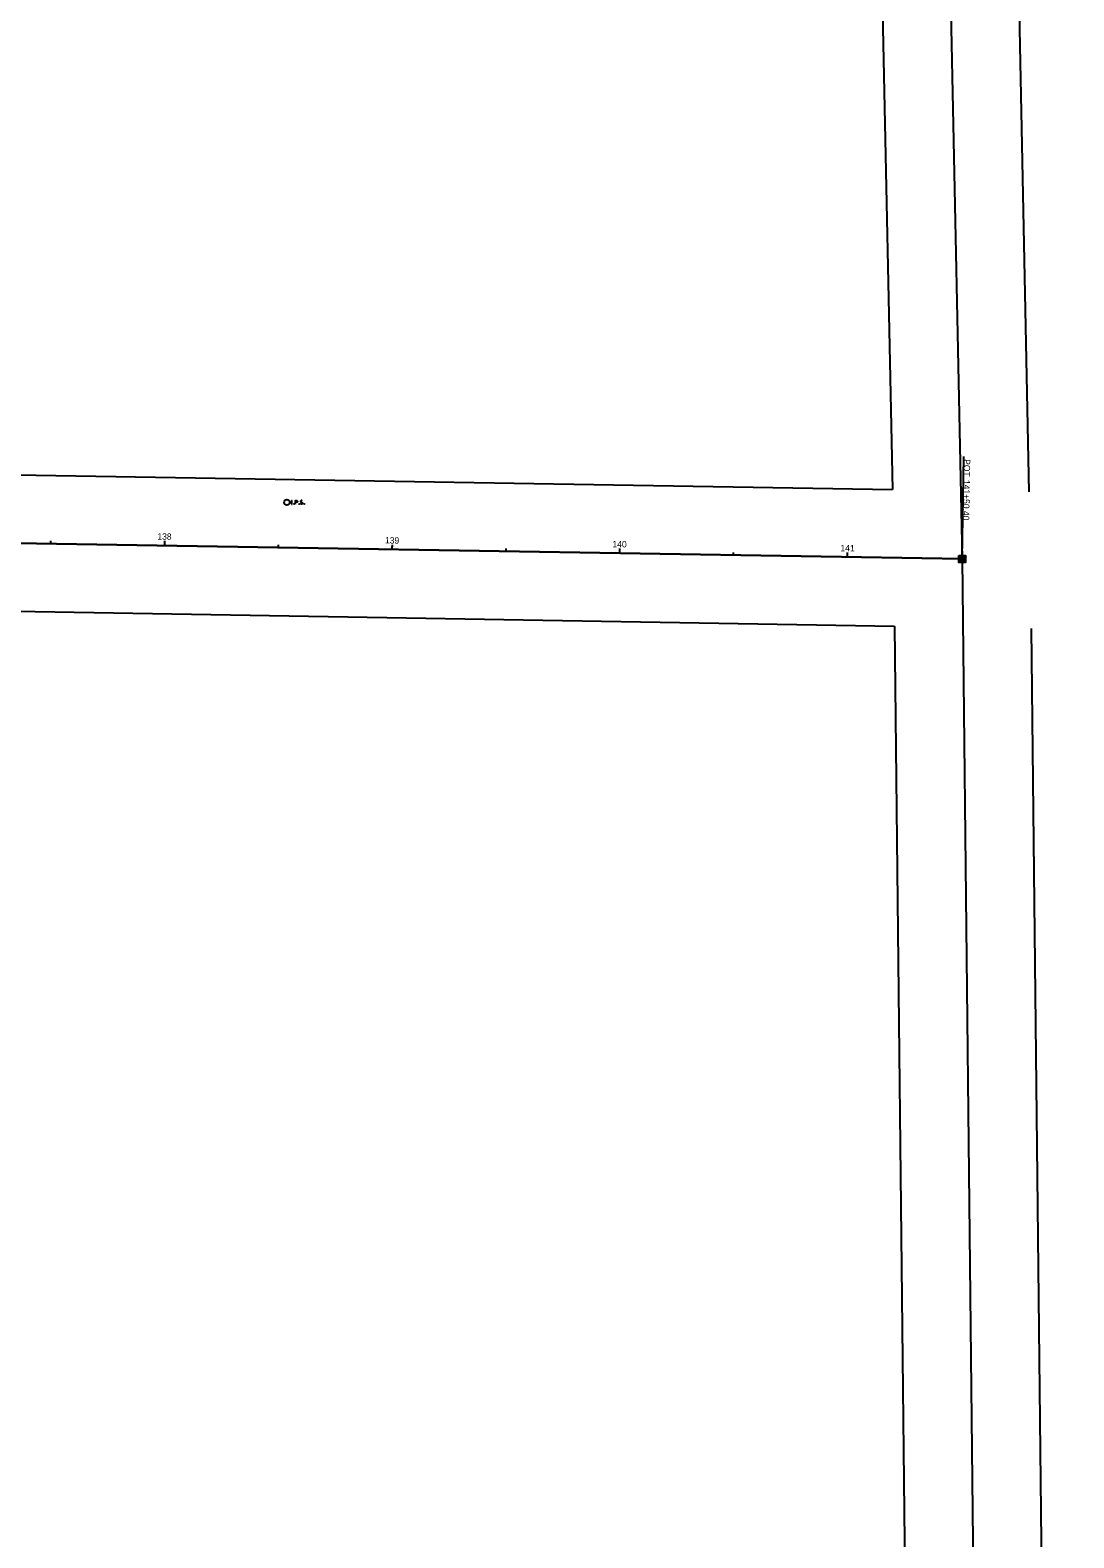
# Model space of a CAD drawing. Extents: x 2003596 to 2006933, y 570827 to 573780.
# Drawn here: x 2006475 to 2006933, y 572153 to 572815 of the extents above; entities that cross this region are included whole.
import ezdxf

# ---------------------------------------------------------------- set-up
doc = ezdxf.new("R2010")
doc.units = 0
for name, color, linetype in [('DT_X_Spot_Elev', 7, 'Continuous'), ('DV_X_Lot_Line', 7, 'Continuous'), ('GE_X_Alignment', 7, 'Continuous'), ('GE_X_Alignment_1000_Cardinal_Points', 7, 'Continuous'), ('GE_X_Alignment_1000_Stations', 7, 'Continuous'), ('GE_X_Alignment_100_Cardinal_Points', 7, 'Continuous'), ('GE_X_Alignment_100_Stations', 7, 'Continuous'), ('GE_X_Alignment_500_Cardinal_Points', 7, 'Continuous'), ('GE_X_Alignment_500_Stations', 7, 'Continuous'), ('RW_X_CL', 7, 'Continuous'), ('RW_X_Esmt_SH', 7, 'Continuous'), ('SC_Scratch9', 7, 'Continuous'), ('SV_P_Mon_Cells_Set', 7, 'Continuous'), ('SV_X_Control_Cells_Found', 7, 'Continuous')]:
    doc.layers.add(name, color=color, linetype=linetype)

msp = doc.modelspace()

# ---------------------------------------------------------------- linework, layer by layer
at = {"layer": 'DT_X_Spot_Elev'}
for p, q in [((2006865.66, 573476.51), (2006884.1, 572582.77)), ((2006884.1, 572582.77), (2006023.62, 572597.25))]:
    msp.add_line(p, q, dxfattribs=at)
at = {"layer": 'DV_X_Lot_Line'}
for p, q in [((2006865.66, 573476.51), (2006884.1, 572582.77)), ((2006884.1, 572582.77), (2006903.2, 570827.76))]:
    msp.add_line(p, q, dxfattribs=at)
at = {"layer": 'GE_X_Alignment'}
msp.add_line((2006023.62, 572597.25), (2006884.1, 572582.77), dxfattribs=at)
at = {"layer": 'GE_X_Alignment_1000_Cardinal_Points'}
msp.add_line((2006884.1, 572582.77), (2006884.86, 572627.76), dxfattribs=at)
msp.add_circle((2006884.1, 572582.77), 0.6, dxfattribs=at)
at = {"layer": 'GE_X_Alignment_1000_Stations'}
msp.add_line((2006733.72, 572585.3), (2006733.75, 572587.3), dxfattribs=at)
at = {"layer": 'GE_X_Alignment_100_Cardinal_Points'}
msp.add_line((2006884.1, 572582.77), (2006884.86, 572627.76), dxfattribs=at)
msp.add_circle((2006884.1, 572582.77), 0.6, dxfattribs=at)
at = {"layer": 'GE_X_Alignment_100_Stations'}
for p, q in [((2006483.76, 572589.51), (2006483.78, 572590.71)), ((2006533.75, 572588.67), (2006533.78, 572590.67)), ((2006583.74, 572587.82), (2006583.76, 572589.02)), ((2006633.73, 572586.98), (2006633.77, 572588.98)), ((2006683.73, 572586.14), (2006683.75, 572587.34)), ((2006733.72, 572585.3), (2006733.75, 572587.3)), ((2006783.71, 572584.46), (2006783.73, 572585.66)), ((2006833.71, 572583.62), (2006833.74, 572585.62)), ((2006883.7, 572582.78), (2006883.72, 572583.98))]:
    msp.add_line(p, q, dxfattribs=at)
at = {"layer": 'GE_X_Alignment_500_Cardinal_Points'}
msp.add_line((2006884.1, 572582.77), (2006884.86, 572627.76), dxfattribs=at)
msp.add_circle((2006884.1, 572582.77), 0.6, dxfattribs=at)
at = {"layer": 'GE_X_Alignment_500_Stations'}
for p, q in [((2006533.75, 572588.67), (2006533.77, 572589.87)), ((2006633.73, 572586.98), (2006633.75, 572588.18)), ((2006733.72, 572585.3), (2006733.75, 572587.3)), ((2006833.71, 572583.62), (2006833.73, 572584.82))]:
    msp.add_line(p, q, dxfattribs=at)
at = {"layer": 'RW_X_CL'}
msp.add_line((2006884.1, 572582.77), (2006023.62, 572597.25), dxfattribs=at)
at = {"layer": 'RW_X_Esmt_SH'}
for p, q in [((2006835.67, 573475.89), (2006853.47, 572613.29)), ((2006895.65, 573477.13), (2006913.5, 572612.28)), ((2006024.45, 572627.24), (2006853.47, 572613.29)), ((2006022.8, 572567.26), (2006854.42, 572553.27)), ((2006854.42, 572553.27), (2006873.21, 570827.44)), ((2006914.44, 572552.26), (2006933.2, 570828.09))]:
    msp.add_line(p, q, dxfattribs=at)
at = {"layer": 'SC_Scratch9'}
msp.add_line((2006884.1, 572582.77), (2006371.52, 572591.34), dxfattribs=at)
at = {"layer": 'SV_P_Mon_Cells_Set'}
msp.add_line((2006884.1, 572582.77), (2006884.1, 572582.77), dxfattribs=at)
for points in [[(2006589.46, 572608.43), (2006589.82, 572608.43)], [(2006589.46, 572606.83), (2006589.82, 572606.83)], [(2006589.64, 572606.83), (2006589.64, 572608.43)], [(2006590.6, 572607.05), (2006590.65, 572607.05), (2006590.69, 572607.02), (2006590.72, 572606.97), (2006590.72, 572606.91), (2006590.69, 572606.86), (2006590.65, 572606.83), (2006590.6, 572606.83), (2006590.57, 572606.86), (2006590.53, 572606.91), (2006590.53, 572606.97), (2006590.57, 572607.02), (2006590.6, 572607.05)], [(2006591.2, 572606.83), (2006591.2, 572608.43), (2006591.73, 572608.43), (2006591.79, 572608.42), (2006591.87, 572608.39), (2006591.9, 572608.37), (2006591.93, 572608.34), (2006591.98, 572608.28), (2006592.01, 572608.22), (2006592.03, 572608.12), (2006592.03, 572607.97), (2006592.02, 572607.92), (2006592, 572607.84), (2006591.95, 572607.75), (2006591.91, 572607.71), (2006591.88, 572607.69), (2006591.82, 572607.66), (2006591.73, 572607.65), (2006591.2, 572607.65)], [(2006592.85, 572607.05), (2006592.9, 572607.05), (2006592.94, 572607.02), (2006592.97, 572606.97), (2006592.97, 572606.91), (2006592.94, 572606.86), (2006592.9, 572606.83), (2006592.85, 572606.83), (2006592.81, 572606.86), (2006592.78, 572606.91), (2006592.78, 572606.97), (2006592.81, 572607.02), (2006592.85, 572607.05)], [(2006594.21, 572608.32), (2006594.19, 572608.34), (2006594.16, 572608.37), (2006594.06, 572608.41), (2006593.94, 572608.43), (2006593.85, 572608.43), (2006593.82, 572608.43), (2006593.67, 572608.39), (2006593.55, 572608.32), (2006593.48, 572608.22), (2006593.45, 572608.12), (2006593.45, 572608.04), (2006593.48, 572607.94), (2006593.56, 572607.85), (2006594.17, 572607.47), (2006594.22, 572607.42), (2006594.25, 572607.37), (2006594.27, 572607.3), (2006594.27, 572607.22), (2006594.26, 572607.15), (2006594.25, 572607.1), (2006594.22, 572607.03), (2006594.2, 572606.98), (2006594.18, 572606.95), (2006594.15, 572606.91), (2006594.11, 572606.88), (2006594.07, 572606.86), (2006594.04, 572606.84), (2006593.94, 572606.83), (2006593.78, 572606.83), (2006593.68, 572606.86), (2006593.54, 572606.95), (2006593.45, 572607.02)], [(2006595.03, 572607.05), (2006595.08, 572607.05), (2006595.12, 572607.02), (2006595.15, 572606.97), (2006595.15, 572606.91), (2006595.12, 572606.86), (2006595.08, 572606.83), (2006595.03, 572606.83), (2006595, 572606.86), (2006594.96, 572606.91), (2006594.96, 572606.97), (2006595, 572607.02), (2006595.03, 572607.05)], [(2006882.6, 572584.27), (2006885.6, 572584.27), (2006885.6, 572581.27), (2006882.6, 572581.27), (2006882.6, 572584.27)], [(2006883.36, 572581.77), (2006883.36, 572583.77), (2006884.1, 572581.77), (2006884.84, 572583.77), (2006884.84, 572581.77)]]:
    msp.add_lwpolyline(points, dxfattribs=at)
msp.add_circle((2006587.44, 572607.63), 1.2, dxfattribs=at)
at = {"layer": 'SV_X_Control_Cells_Found'}
for p, q in [((2006883.3, 572582.17), (2006882.33, 572581.45)), ((2006885.87, 572584.09), (2006884.91, 572583.37))]:
    msp.add_line(p, q, dxfattribs=at)
msp.add_lwpolyline([(2006883.65, 572583.97), (2006884.55, 572583.97), (2006885.26, 572582.77), (2006884.55, 572581.57), (2006883.65, 572581.57), (2006882.94, 572582.77)], close=True, dxfattribs=at)

# ---------------------------------------------------------------- texts
at = {"layer": 'GE_X_Alignment_1000_Cardinal_Points'}
for s, p in [('POT', (2006884.89, 572626.64)), ('141+50.40', (2006884.73, 572617.51))]:
    msp.add_text(s, height=2.8, rotation=269.03593, dxfattribs=at).set_placement(p)
at = {"layer": 'GE_X_Alignment_1000_Stations'}
msp.add_text('140', height=2.8, rotation=359.03593, dxfattribs=at).set_placement((2006730.48, 572587.9))
at = {"layer": 'GE_X_Alignment_100_Cardinal_Points'}
for s, p in [('POT', (2006884.89, 572626.64)), ('141+50.40', (2006884.73, 572617.51))]:
    msp.add_text(s, height=2.8, rotation=269.03593, dxfattribs=at).set_placement(p)
at = {"layer": 'GE_X_Alignment_100_Stations'}
for s, p in [('138', (2006530.51, 572591.27)), ('139', (2006630.53, 572589.58)), ('140', (2006730.48, 572587.9)), ('141', (2006830.64, 572586.17))]:
    msp.add_text(s, height=2.8, rotation=359.03593, dxfattribs=at).set_placement(p)
at = {"layer": 'GE_X_Alignment_500_Cardinal_Points'}
for s, p in [('POT', (2006884.89, 572626.64)), ('141+50.40', (2006884.73, 572617.51))]:
    msp.add_text(s, height=2.8, rotation=269.03593, dxfattribs=at).set_placement(p)
at = {"layer": 'GE_X_Alignment_500_Stations'}
msp.add_text('140', height=2.8, rotation=359.03593, dxfattribs=at).set_placement((2006730.48, 572587.9))

doc.saveas('drawing.dxf')
